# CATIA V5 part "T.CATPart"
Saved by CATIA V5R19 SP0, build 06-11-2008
Part number: T
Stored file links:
  G:\EU_thinkMotion\CFAO_2010\MMS_groupe3\MMS_groupe3\A reprendre\evulliez\evulliez\T.CATPart

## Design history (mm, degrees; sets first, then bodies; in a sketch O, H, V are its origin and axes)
Body1 (main body)
  Point1: (0, 0, 0)
  Line1: type PtDir, RefPoint Point1, Direction (0, 0, 1), Start -50, End 50
  Plane1: type Offset, RefPlane xy-plane, Offset 0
